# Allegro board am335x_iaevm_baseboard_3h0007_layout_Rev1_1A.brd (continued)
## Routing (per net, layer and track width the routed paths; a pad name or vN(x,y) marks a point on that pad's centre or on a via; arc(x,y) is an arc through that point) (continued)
AM335X_OSC0_OUT: length 11.4
  TOP w0.121: U2.U11 91.43,86.63 92.82,86.63 93.37,87.17 94.36,87.17 95.32,86.21 98.78,86.21 100.06,84.93 100.52,84.93 R8.1
AM335X_OSC1_IN: length 15.2
  TOP w0.102: 77.74,81.97 77.97,81.97 U2.A6
  TOP w0.121: Y1.4 64.93,79.11 65.71,79.9 65.86,79.9 66.71,80.74 C2.2 67.42,80.77 67.45,80.8 68.46,80.8 68.83,80.43 71.12,80.43 71.35,80.66 72.66,80.66 73.32,81.32 75.69,81.32 76.01,81.64 76.42,81.64 76.43,81.63 77.2,81.63 77.22,81.6 77.36,81.6 77.74,81.97
AM335X_OSC1_OUT: length 8.5
  TOP w0.102: U2.A4 77.91,80.89 77.1,80.89
  TOP w0.121: 77.1,80.89 76.32,80.89 75.34,79.91 71.66,79.91 71.27,79.53 70.95,79.53 70.84,79.41 R5.1
AM335X_PORZ: length 21
  TOP w0.102: 78.08,89.83 78.58,89.83 79,89.41 U2.B15
  TOP w0.121: 78.08,89.83 76.52,89.83 76.16,90.19 v1(76.16,90.46) ; v1(70.52,100.81) 69.57,101.76 R9.2
  BOTTOM w0.121: v1(70.52,100.81) 72.76,100.81 74.33,99.23 74.33,92.29 v1(76.16,90.46)
AM335X_RTC_PORZ: length 43
  TOP w0.102: 76.32,81.39 77.49,81.39 77.86,81.76 78.65,81.76 79,81.41 U2.B5
  TOP w0.121: U1.3 60.48,99.86 v1(60.24,100.11) 60.48,100.36 U1.2 ; 76.32,81.39 76.12,81.39 75.79,81.06 73.44,81.06 72.79,80.41 71.45,80.41 71.22,80.17 68.73,80.17 68.55,80.36 v1(68.11,80.36)
  LY3 w0.133: v1(68.11,80.36) 62.21,80.36 61.93,80.64 v1(61.93,80.68)
  BOTTOM w0.121: R4.2 60.74,100.62 v1(60.24,100.11) 59.71,99.59 59.71,97.92 59.22,97.42 59.22,89.66 59.22,89.05 60.36,87.91 60.36,87.52 60.36,87.52 60.36,86.91 61.08,86.18 61.08,83.28 61.71,82.64 61.71,80.9 v1(61.93,80.68)
AM335X_SPI0_CS0: length 77.4
  TOP w0.102: U2.A16 77.1,90.2
  TOP w0.121: 131.23,95.29 129.4,95.29 v1(129.35,95.34) ; v2(76.9,90.25) 76.94,90.2 77.1,90.2
  LY3 w0.133: v1(72.13,100.28) 73.56,101.7 82.75,101.7 83.22,101.23 92.14,101.23 97.11,96.25 116.29,96.25 117.21,95.34 v1(129.35,95.34)
  BOTTOM w0.121: v1(72.13,100.28) 72.73,99.68 72.73,96.78 72.17,96.22 R552.1 72.77,95.58 73.38,95.58 74.08,94.87 74.08,91.91 76.03,89.97 76.62,89.97 v2(76.9,90.25)
AM335X_SPI0_CS1: length 10.4
  TOP w0.102: v2(79.4,89.8) U2.C15
  TOP w0.121: v1(73.01,90.83) 73.02,90.84 73.02,91.16 72.61,91.56 72.61,91.82 72.3,92.13 R380.2 72.29,92.19 71.33,92.19 R78.2
  BOTTOM w0.102: 77.1,89.72 79.32,89.72 v2(79.4,89.8)
  BOTTOM w0.121: 77.1,89.72 73.73,89.72 73.01,90.44 v1(73.01,90.83)
AM335X_SPI0_D0: length 107.8
  TOP w0.102: U2.B17 78.67,91.33 77.33,91.33 77.21,91.45 77.1,91.45
  TOP w0.121: v1(76.11,133.44) 78.83,133.44 R205.1 ; 77.1,91.45 75.89,91.45 v1(75.63,91.71)
  BOTTOM w0.121: v1(76.11,133.44) 76.11,133.45 75.98,133.58 70.52,133.58 70.4,133.45 70.4,133.06 70.52,132.93 75.2,132.93 75.32,132.8 75.32,132.4 75.2,132.27 70.52,132.27 70.4,132.14 70.4,131.79 70.52,131.66 75.4,131.66 75.53,131.53 75.53,131.15 75.4,131.02 70.52,131.02 70.4,130.9 70.4,130.52 70.52,130.39 75.6,130.39 75.73,130.26 75.73,129.91 75.6,129.78 70.85,129.78 70.73,129.65 70.73,129.26 70.85,129.13 73.6,129.13 73.72,129 73.72,120.18 75.98,117.92 75.98,111.75 76.11,111.62 76.34,111.62 76.47,111.49 76.47,105.7 76.34,105.57 75.96,105.57 75.83,105.7 75.83,110.76 75.7,110.88 75.27,110.88 75.14,110.76 75.14,105.07 75.27,104.94 75.99,104.94 76.12,104.81 76.12,104.35 75.99,104.23 75.27,104.23 75.14,104.1 75.14,103.64 75.27,103.52 76.02,103.52 76.14,103.39 76.14,102.96 76.02,102.83 75.27,102.83 75.14,102.7 75.14,102.31 75.98,101.47 75.98,100.14 75.37,99.53 75.37,97.67 75.25,97.54 74.71,97.54 74.58,97.41 74.58,96.73 74.71,96.61 75.61,96.61 75.74,96.48 75.74,95.8 75.61,95.67 74.71,95.67 74.58,95.54 74.58,92.39 75.27,91.71 v1(75.63,91.71)
AM335X_SPI0_D1: length 15
  TOP w0.102: U2.B16 78.67,90.2 78.28,90.59 77.24,90.59 77.1,90.73
  TOP w0.121: R177.1 71.54,93.76 71.99,93.32 72.37,93.32 v1(72.81,92.87) 73.06,92.62 73.74,92.62 75.46,90.9 76.92,90.9 77.1,90.73
  BOTTOM w0.121: v1(72.81,92.87) 72.81,94.4 R553.1
AM335X_SPI0_SCLK: length 8
  TOP w0.102: 77.1,91.13 77.23,91 U2.A17 ; 77.08,91.15 76.87,91.15
  TOP w0.121: 77.1,91.13 77.08,91.15 ; 76.87,91.15 75.56,91.15 72.44,94.27 R201.1
AM335X_UART0_CTSN: length 13.9
  TOP w0.102: U2.E18 81.51,91.91 81.51,92.78
  TOP w0.121: 81.51,92.78 80.93,93.36 80.93,95.53 81.07,95.67 81.07,96.86 81.94,97.74 81.94,98.43 81.27,99.11 81.27,99.89 79.29,101.87 79.29,103.16 R61.2
AM335X_UART0_RTSN: length 10.7
  TOP w0.102: 80.68,92.9 80.68,92.37 81.06,91.99 81.06,91.35 81.4,91.01 U2.E17
  TOP w0.121: 80.68,92.9 80.68,95.72 80.82,95.85 80.82,96.99 81.66,97.83 81.66,97.83 81.69,97.87 81.69,98.33 80.79,99.23 80.17,99.23 R362.2
AM335X_UART0_RXD: length 103.8
  TOP w0.102: v2(81,89.8) U2.E15
  TOP w0.121: v1(78.64,105.09) 78.44,104.9 78.13,104.9 77.35,104.12 77.35,103.52 78.4,102.48 78.4,100.2 78.15,99.95 78.15,99.52 78.57,99.1 79.16,99.1 R363.2 80.17,97.43 80.57,97.03 80.57,96.04 80.22,95.69 v1(80.22,95.46) ; v1(52.62,64.73) 52.62,62.9 R249.2
  LY3 w0.133: v1(51.14,107.12) 51.48,107.46 51.48,107.59 51.74,107.85 51.87,107.85 51.9,107.89 53.17,107.89 54.52,106.54 77.13,106.54 78.56,105.1 78.62,105.1 v1(78.64,105.09)
  BOTTOM w0.102: v2(81,89.8) 81,89.83 80.58,90.24 80.58,90.97 ; 80.35,93.04 80.35,91.2 80.54,91.01
  BOTTOM w0.121: 80.54,91.01 80.58,90.97 ; v1(80.22,95.46) 80.22,95.22 80.35,95.08 80.35,93.04 ; v1(51.14,107.12) 47.43,107.12 44.84,104.53 44.84,103.38 44.81,103.35 44.81,98.78 44.64,98.61 44.64,94.02 45.12,93.53 45.12,80.81 44.35,80.04 43.12,78.8 43.12,72.96 48.45,67.63 50.56,67.63 52.62,65.57 v1(52.62,64.73)
AM335X_UART0_TXD: length 14.6
  TOP w0.102: v2(81,90.6) U2.E16
  TOP w0.121: v1(78.84,96.15) 78.42,96.57 73.31,96.57 R361.2
  BOTTOM w0.102: v2(81,90.6) 81,91.15 80.66,91.49 80.66,92.9
  BOTTOM w0.121: 80.66,92.9 80.66,95.67 80.4,95.92 79.08,95.92 78.85,96.15 v1(78.84,96.15)
AM335X_UART1_CTSN: length 17
  TOP w0.102: 80.41,91.99 U2.D18
  TOP w0.121: 80.41,91.99 80.41,94.64 79.77,95.28 79.77,96 80.13,96.36 v1(80.13,96.36) ; R84.2 75.86,103.54 76.56,103.54 v1(76.56,103.54)
  BOTTOM w0.121: v1(80.13,96.36) 79.99,96.36 79.77,96.58 79.31,96.58 79.08,96.81 79.08,99.07 78.9,99.25 78.9,100.66 79.46,101.22 79.46,102.2 78.62,103.03 77.07,103.03 v1(76.56,103.54)
AM335X_UART1_RTSN: length 15.2
  TOP w0.102: U2.D17 80.59,91 80.24,91.35 80.24,91.85
  TOP w0.121: v1(76.7,101.23) 76.7,100.95 R229.1 76.74,99.99 76.74,98.34 77.57,97.51 79.68,97.51 79.68,97.51 79.75,97.51 80.01,97.25 80.01,96.88 79.53,96.4 79.53,95.18 80.17,94.54 80.17,91.92 80.24,91.85
  BOTTOM w0.121: v1(76.7,101.23) 77.18,101.23 77.76,100.65 77.76,100.62
AM335X_UART1_RXD: length 15.1
  TOP w0.102: v2(80.2,90.6) U2.D16
  TOP w0.121: v1(75.93,98.94) 75.65,99.23 73.16,99.23 72.68,99.71 72.68,99.73
  LY4 w0.102: v2(80.2,90.6) 79.42,91.38 78.02,91.38 77.61,91.78 77.61,92.75 77.46,92.9
  LY4 w0.133: 77.46,92.9 77.46,94.83 76.69,95.59 76.69,98.18 v1(75.93,98.94)
AM335X_UART1_TXD: length 13.8
  TOP w0.102: v2(80.2,89.8) U2.D15
  TOP w0.121: R91.2 74.84,97.9 v1(74.92,97.98)
  LY4 w0.102: v2(80.2,89.8) 80.2,89.83 79.81,90.22 77.7,90.22 77.1,90.82
  LY4 w0.133: v1(74.92,97.98) 74.93,97.97 74.93,91.36 75.35,90.94 76.97,90.94 77.1,90.82
AM335X_USB0_CE: length 13.7
  TOP w0.102: v2(87.4,89.8) U2.M15
  TOP w0.121: TP23.1 93.14,98.59 93.64,99.09 v1(93.64,99.1)
  LY3 w0.133: v2(87.4,89.8) 87.4,89.81 87.8,90.21 87.8,90.46 87.8,90.46 87.8,90.76 87.86,90.82 87.86,93.17 90.44,95.74 90.44,96.68 92.87,99.12 93.61,99.12 v1(93.64,99.1)
AM335X_USB0_DRVVBUS: length 108.1
  TOP w0.102: U2.F16 v2(81.8,90.6)
  TOP w0.121: U22.4 137.87,145.15 v1(138.42,144.6)
  LY3 w0.133: v1(138.42,144.6) 137.36,143.55 121.45,143.55 118.66,140.75 101.51,140.75 95.52,134.76 84.87,134.76 v1(84.01,133.9)
  LY4 w0.133: v2(81.8,90.6) 81.8,90.71 80.12,92.39 80.12,94.7 79.55,95.28 79.55,96.41 80.01,96.88 80.01,97.61 79.74,97.88 79.74,103.74 80.68,104.68 80.68,116.42 83.42,119.15 83.42,133.17 84.01,133.77 v1(84.01,133.9)
  BOTTOM w0.121: R383.1 137.35,144.6 v1(138.42,144.6)
AM335X_USB0_VBUS: length 17.2
  TOP w0.254: D9.1 96.3,96.24 R563.2 ; v2(89,89.8) U2.P15
  TOP w0.508: R563.2 95.99,97.05 v1(94.84,97.05)
  LY3 w0.127: 89.01,91.27 89.41,90.88 89.41,90.21 v2(89,89.8)
  LY3 w0.133: 89.01,91.27 88.6,90.86 88.6,90.2 v2(89,89.8)
  LY3 w0.508: 89.01,91.27 89.01,93.69 91.99,96.66 91.99,97.01 92.47,97.5 94.39,97.5 v1(94.84,97.05)
AM335X_USB1_CE: length 6
  TOP w0.102: U2.P18 88.6,92.9
  TOP w0.121: 88.6,92.9 88.6,93.32 89.79,94.52 90.45,94.52 91.35,95.41 TP36.1
AM335X_USB1_DRVVBUS: length 136.3
  TOP w0.102: U2.F15 v2(81.8,89.8)
  TOP w0.121: U29.4 v1(146.58,144.83)
  LY3 w0.133: v1(81.83,133.87) 82.43,133.26 85.51,133.26 86.6,134.35 95.74,134.35 101.76,140.37 118.91,140.37 121.7,143.17 138.85,143.17 142.53,139.48 142.53,133.77 v1(143.36,132.94)
  LY4 w0.133: v1(81.83,133.87) 81.83,130.15 81.32,129.64 81.32,119.19 80.28,118.15 80.28,104.79 79.03,103.54 79.03,96.76 79.29,96.51 79.29,95.17 79.68,94.78 79.68,92.48 81.4,90.76 81.4,90.2 v2(81.8,89.8)
  BOTTOM w0.121: R387.1 146.21,145.2 v1(146.58,144.83) 146.58,143.09 146.34,142.85 145.33,142.85 145.01,142.53 145.01,137.51 143.42,135.93 143.42,133.01 v1(143.36,132.94)
AM335X_USB1_VBUS: length 12.8
  TOP w0.254: v1(90.37,101.71) 90.37,101.28 D10.1 ; U2.T18 v2(90.2,92.37)
  TOP w0.508: R564.2 90.37,102.73 v1(90.37,101.71)
  LY4 w0.508: v1(90.37,101.71) 90.37,101.22 90.54,101.05 90.54,98.59 89.78,97.83 89.78,94.63 89.37,94.22 89.37,92.94 89.86,92.45 90.12,92.45 v2(90.2,92.37)
AM335X_VDDA_ADC: length 42.7
  TOP w0.381: v2(80.2,83.4) U2.D8
  TOP w0.508: v1(49.31,74.43) v1(59,74.43) ; v1(59.54,81.68) 60.17,81.68 60.28,81.57 64.38,81.57 64.49,81.46 65.8,81.46 66.12,81.79 69.29,81.79 70.21,80.87 70.26,80.87 70.26,80.87 70.79,80.87 71.02,81.1 72.27,81.1 73.32,82.14 76.58,82.14 76.64,82.08 v1(76.82,82.08)
  BOTTOM w0.152: v1(76.82,82.08) 77.19,82.08 77.82,82.71 79.67,82.71 80.2,83.25 v2(80.2,83.4)
  BOTTOM w0.508: v1(59,74.43) 59.54,74.97 59.54,79.68 59.52,79.7 59.52,81.66 v1(59.54,81.68) ; R501.1 v1(49.31,74.43) 49.6,74.71 50.33,74.71
AM335X_VDDS: length 39.8
  TOP w0.305: v2(81,81.8) U2.E6
  TOP w0.381: v2(89,89) U2.P14 ; v2(89,84.2) U2.P9 ; v2(85.8,88.2) U2.K13 ; v2(82.6,84.2) U2.F9 ; U2.E14 v2(81,89) ; v2(88.2,81.8) U2.N6
  TOP w0.635: v1(99.99,111.54) 99.15,111.54 97.08,109.47 88.8,109.47 v1(88.21,108.88)
  LY4 w0.635: v1(87.42,99.11) 87.42,100.27 88.07,100.93 88.07,108.74 v1(88.21,108.88)
  BOTTOM w0.102: 81.42,90.21 82.08,90.21 82.21,90.33 82.21,91.1 C96.1 81.42,91.07 81.42,90.21 ; 81.42,90.21 81.42,89.68 81,89.26 v2(81,89)
  BOTTOM w0.508: C50.1 92.43,89.68 92.71,89.95 92.75,89.95 v1(92.82,90.03) 92.82,90.16 92.45,90.52 C48.1
  BOTTOM w0.635: C249.1 99.99,110.43 v1(99.99,111.54) 99.99,112.18 C89.1 100.75,115.32 R498.1
  vias: v1(93.43,90.33)
AM335X_VDDS_DDR: length 54.2
  TOP w0.381: U2.E5 v2(81.8,81) U2.F5 ; U2.K5 v2(85.8,81) U2.L5 ; U2.H5 v2(84.2,81) U2.J5 ; v2(82.6,81) U2.G5
  TOP w0.635: R508.2 115.7,69.44 116.29,68.85 116.29,65.75 115.6,65.06 110.78,65.06 110.78,65.17 108.24,67.71 C233.1 104.73,68.43 104.44,68.43 103.95,68.92 103.95,70.67 101.75,72.87 98.99,72.87 98.74,73.13 v1(97.62,73.13) v1(97.04,73.13) v1(96.43,73.13)
  LY3 w0.635: v1(96.43,73.13) v1(97.04,73.13) v1(97.62,73.13)
  LY4 w0.635: 92.34,82.38 92.65,82.08 93.54,82.08 94.02,81.6 94.02,80.56 94.53,80.05 94.53,77.76 96.43,75.86 v1(96.43,73.13) v1(97.04,73.13) v1(97.62,73.13)
  BOTTOM w0.381: v2(81.8,81) 81.76,81.04 C77.1 ; C79.1 84.26,80.94 v2(84.2,81) ; C78.1 85.86,80.94 v2(85.8,81) ; C82.1 v1(97.62,73.13) ; v1(96.43,73.13) 96.31,73 95.61,73 C80.1 ; v2(82.6,81) 83.3,81.7 C76.1
  BOTTOM w0.635: v1(96.43,73.13) v1(97.04,73.13) v1(97.62,73.13)
AM335X_VDDSHV1: length 54
  TOP w0.381: U2.P8 v2(89,83.4) U2.P7
  LY3 w0.102: 91.74,82.52 91.43,82.21 89.45,82.21 89,82.65 v2(89,83.4) 89.26,83.4 89.64,83.02 89.65,83.02 89.69,82.98 91.29,82.98
  LY3 w0.508: 91.29,82.98 92.06,82.21 95.67,82.21 98.34,79.54 99.16,79.54 99.8,80.17 v1(99.99,80.17) 100.62,80.81 100.62,81.95 101.38,82.71 v1(102.91,82.71) 103.54,83.35 107.1,83.35 v1(108.37,82.08)
  BOTTOM w0.381: C31.1 88.31,83.4 v2(89,83.4)
  BOTTOM w0.508: v1(99.99,80.17) 100.49,79.67 101.38,79.67 101.65,79.4 C258.1 ; C32.1 103.8,82.71 v1(102.91,82.71) ; v1(108.37,82.08) 115.48,74.97 120.69,74.97 122.11,73.54 R493.1
AM335X_VDDSHV2: length 39.3
  TOP w0.381: U2.P10 88.6,85.46 88.72,85.58 88.72,86.02 88.6,86.14 U2.P11 v2(89,86.6)
  TOP w0.508: C259.1 97.89,86.7 v1(95.85,86.7) 95.85,87.59 C92.1
  LY3 w0.635: v1(115.42,95.03) 110.5,95.03 108.29,92.82 102.4,92.82 101.12,91.54 101.12,89.74 99.11,87.73 96.87,87.73 v1(95.85,86.7) 95.07,86.7 94.73,87.04 93.69,87.04 93,86.35 93,86.35 92.45,85.8 89.68,85.8 89.15,86.33 89.15,86.45 v2(89,86.6)
  BOTTOM w0.381: C90.1 89,85.95 v2(89,86.6)
  BOTTOM w0.635: R545.1 114.43,95.03 v1(115.42,95.03)
AM335X_VDDSHV3: length 96.8
  TOP w0.381: v2(89,88.2) U2.P13 ; U2.P12 v2(89,87.4)
  TOP w0.635: R546.1 v1(135,140.59)
  LY3 w0.635: v1(110.65,135.93) 132.24,135.93 134.4,138.09 134.4,139.99 v1(135,140.59) ; 93.17,87.97 93.24,87.97 93.28,87.92 94.97,87.92 96.42,89.37 v1(96.48,89.37) 96.85,89.37 97.14,89.66 97.14,90.06 97.18,90.1 97.18,90.67 97.14,90.71 97.14,90.99 97.94,91.79 99.54,91.79 100.37,92.62 100.9,92.62 101.87,93.59 v1(102.31,93.59) 102.54,93.81 107.65,93.81 108.77,94.93 v1(108.77,95.13)
  LY4 w0.635: v1(110.65,135.93) 109.89,135.17 109.89,105.57 111.54,103.92 111.54,101.15 110.55,100.16 110.55,96.71 108.97,95.13 v1(108.77,95.13)
  BOTTOM w0.381: v2(89,87.4) v2(89,88.2) 88.28,88.2 C94.1
  BOTTOM w0.508: C273.1 102.85,93.59 v1(102.31,93.59) ; C93.1 97.19,90 96.56,89.37 v1(96.48,89.37)
AM335X_VDDSHV4: length 99.8
  TOP w0.381: U2.J14 v2(84.2,89) U2.H14
  TOP w0.635: v1(122.47,133.7) 130.47,133.7 131.1,133.07 v1(133.58,133.07)
  LY3 w0.635: v1(119.67,116.06) 118.2,114.59 v1(83.13,114.59)
  LY4 w0.635: v2(84.2,89) 84.53,89 84.92,89.39 84.92,91.25 85.56,91.88 85.56,94.3 85.1,94.75 85.08,94.75 84.49,95.34 84.49,95.54 v1(84.44,95.59)
  BOTTOM w0.635: v1(83.13,114.59) 83.13,97.21 83.64,96.7 C274.1 v1(84.44,95.59) 83.6,94.75 C43.1 ; v1(133.58,133.07) 134.69,133.07 R494.1 ; C42.1 84.07,89.13 v2(84.2,89) ; v1(119.67,116.06) 119.73,116.13 119.73,129.64 122.47,132.37 v1(122.47,133.7)
AM335X_VDDSHV5: length 73.1
  TOP w0.381: U2.K14 v2(85.8,89) U2.L14
  TOP w0.635: v1(94.35,131.23) 94.58,131 97.97,131 v1(98.65,131.69)
  LY4 w0.102: v2(85.8,89) 85.8,89.03 85.42,89.41 85.42,90.82 85.74,91.13 86.18,91.13 86.18,89.38 v2(85.8,89) ; v2(85.8,89) 86.71,89 86.98,89.27 86.98,90.76 86.97,90.77 86.97,91.48
  LY4 w0.508: 86.18,91.13 86.52,91.48 86.97,91.48 88.68,93.19 88.68,94.26 88.71,94.29 88.71,94.53 89.06,94.88 v1(89.06,96.4)
  BOTTOM w0.635: v1(94.35,131.23) 93.71,130.59 93.71,122.21 90.27,118.77 90.27,113.23 90.8,112.7 90.8,108.18 91.79,107.19 91.79,104.42 90.42,103.05 C257.1 91.07,102.31 91.07,101.15 91.6,100.62 91.6,98.52 90.15,97.07 89.06,97.07 v1(89.06,96.4) ; v1(98.65,131.69) 98.72,131.75 98.72,140.63 99.35,141.26 R495.1 ; v2(85.8,89) 85.94,89.14 C46.1
AM335X_VDDSHV6: length 16.9
  TOP w0.381: U2.E10 v2(81,85.8) U2.E11 v2(81,86.6) U2.E12 ; U2.P5 v2(89,81) ; U2.P5 v2(88.2,81) U2.N5 ; U2.P5 v2(89,81.8) U2.P6 ; U2.G14 v2(82.6,89) U2.F14 ; U2.E13 v2(81,88.2)
  TOP w0.635: C28.1 50.33,85.05 v1(50.31,85.07)
  BOTTOM w0.381: 70.9,83.48 70.14,83.48 v1(69.76,83.1) ; C47.1 77.76,90.77 77.2,91.32 v2(77.2,91.88)
  BOTTOM w0.635: C27.1 82.47,89.13 v2(82.6,89) ; C25.1 92.24,81.69 92.37,81.57 v2(92.37,81.37) ; v2(92.91,79.51) 93.1,79.51 93.31,79.29 93.69,79.29 C29.1 ; R496.1 50.31,86.85 v1(50.31,85.07) 51.51,85.07 C247.1
AM335X_XDMA_EVENT_INTR0: length 16
  TOP w0.102: U2.A15 77.27,89.4 77.17,89.5
  TOP w0.121: 77.17,89.5 76.5,89.5 74.83,91.17 v1(73.95,91.17) ; 66.71,95.03 66.74,95.03 67.19,95.49 70.93,95.49 71.46,94.96 73.16,94.96 v1(73.57,94.55)
  BOTTOM w0.121: v1(73.95,91.17) 73.57,91.55 v1(73.57,94.55)
AM335X_XDMA_EVENT_INTR1: length 31.6
  TOP w0.102: v2(80.2,89) U2.D14
  TOP w0.121: R77.2 63.73,92.3 v1(63.66,92.3)
  LY3 w0.133: v1(63.54,95.8) 64.55,96.81 74.71,96.81 v1(75.98,98.08)
  BOTTOM w0.102: v2(80.2,89) 80.2,89.16 79.78,89.58 79.78,89.96 79.53,90.21 79.51,90.21 79.51,90.21 78.17,90.21
  BOTTOM w0.121: v1(75.98,98.08) 75.98,95.44 74.84,94.3 74.84,92.82 75.4,92.26 75.7,92.26 77.75,90.21 78.17,90.21 ; v1(63.66,92.3) 63.54,92.43 v1(63.54,95.8)
CAP_VBB_MPU: length 4.2
  TOP w0.102: U2.C10 79.41,85.79 v2(79.41,85.8)
  BOTTOM w0.102: 77.22,85.8 v2(79.41,85.8)
  BOTTOM w0.121: 77.22,85.8 77.09,85.8 76.62,86.27 C72.1
CAP_VDD_SRAM_CORE: length 12.4
  TOP w0.102: v2(80.2,85) U2.D9
  TOP w0.121: C60.1 70.01,86.66 71.58,86.66 71.95,87.02 74.63,87.02 75.13,86.52 75.75,86.52 76.59,85.68 v1(76.59,85.42)
  BOTTOM w0.102: v2(80.2,85) 79.94,85 79.56,85.38 78.74,85.38 78.56,85.2 77.73,85.2
  BOTTOM w0.121: 77.73,85.2 77.52,85.42 v1(76.59,85.42)
CAP_VDD_SRAM_MPU: length 5.7
  TOP w0.102: v2(80.2,86.6) U2.D11
  BOTTOM w0.102: v2(80.2,86.6) 80.01,86.79 78.26,86.79 77.63,87.42
  BOTTOM w0.121: C71.1 75.85,87.42 77.63,87.42
DDR_A0: length 57.5
  TOP w0.076: U31.H8 v1(93.16,57.44) ; v1(70.94,57.44) U8.H8
  TOP w0.121: v1(85,55.22) 85,56.81 85.64,57.44 85.64,61.91 86.84,63.12 86.84,63.95 86.25,64.54 86.25,66.8 86.25,67.11 83.22,70.14 v1(83.22,70.97)
  BOTTOM w0.076: 75.07,56.74 73.76,58.05 71.51,58.05 70.94,57.47 v1(70.94,57.44) ; 93.62,56.97 v1(93.16,57.44)
  BOTTOM w0.121: v1(83.22,70.97) 81.25,70.97 80.49,71.73 R18.2 ; 93.62,56.97 93.62,56.82 93.75,56.69 94.08,56.69 94.21,56.57 94.21,53.5 94.08,53.38 86.59,53.38 86.46,53.5 86.46,54.83 86.33,54.96 85.7,54.96 85.44,55.22 v1(85,55.22) 81.39,55.22 81.26,55.09 81.25,55.09 80.81,54.65 75.27,54.65 75.14,54.77 75.14,56.29 75.07,56.36 75.07,56.74
DDR_A1: length 70.1
  TOP w0.076: v1(93.61,61.25) 93.61,60.82 93.72,60.7 93.72,60.24 93.85,60.11 96.81,60.11 96.94,59.98 96.94,59.73 97.07,59.6 98.21,59.6 98.34,59.73 98.34,60.24 98.21,60.36 94.27,60.36 93.98,60.65 93.98,61.71 93.85,61.84 U31.H3 ; U8.H3 71.34,60.73 71.16,60.55 ; v1(70.94,61.44) 70.56,61.06 68.71,61.06 68.7,61.04 68.47,61.04
  TOP w0.121: 71.16,60.55 68.49,60.55 68.36,60.68 68.36,60.93 68.47,61.04 ; v1(87.86,62.39) 87.86,61.79 86.77,60.7 86.5,60.7 86.38,60.83 86.38,61.61 87.63,62.86 87.63,63.21 87.75,63.33 88.01,63.33 88.13,63.45 88.13,63.69 88.01,63.81 87.75,63.81 87.63,63.93 87.63,64.17 87.75,64.29 88.01,64.29 88.13,64.41 88.13,64.65 88.01,64.77 87.75,64.77 87.63,64.9 87.63,65.92 87.44,66.11 87.44,66.75 84.17,70.01 84.17,71.03 R21.2
  BOTTOM w0.076: v1(70.94,61.44) 71.35,61.85 71.35,63.22 71.41,63.28 77.91,63.28 ; 89.24,60.69 89.63,60.3 91.22,60.3 91.35,60.43 91.35,60.68 91.48,60.81 92.49,60.81 92.62,60.68 92.62,60.43 92.75,60.3 94.3,60.3 94.4,60.39 94.4,60.52 94.3,60.62 93.74,60.62 93.61,60.74 v1(93.61,61.25)
  BOTTOM w0.121: 77.91,63.28 79.43,63.28 79.8,62.91 80.25,62.91 82.65,62.91 82.95,63.21 84.47,63.21 85.16,62.52 86.21,62.52 86.33,62.39 86.33,62.11 86.46,61.98 87.76,61.98 87.86,62.08 v1(87.86,62.39) 87.54,62.71 87.29,62.71 87.16,62.84 87.16,63.09 87.29,63.22 87.73,63.22 88.56,62.39 88.56,61.95 88.43,61.82 88.43,61.63 89.01,61.05 89.04,61.05 89.16,60.92 89.16,60.77 89.24,60.69
DDR_A2: length 57.1
  TOP w0.076: v1(93.16,59.04) U31.H7 ; v1(70.94,59.04) U8.H7
  TOP w0.121: v1(84.05,58.39) 84.05,58.84 83.92,58.97 83.79,58.97 83.67,59.1 83.67,60.17 83.79,60.3 83.86,60.3 83.99,60.43 83.99,61.96 84.36,62.34 84.36,62.7 84.11,62.95 84.11,66.11 82.66,67.57 82.66,68 81.26,69.4 80.8,69.4 80.37,69.84 80.37,70.59 80.37,70.6 v1(80.37,70.6)
  BOTTOM w0.076: v1(93.16,59.04) 93.45,59.04 93.57,58.91 93.57,58.33 93.45,58.2 93.13,58.2 93,58.33 93,58.46 92.87,58.58 92.68,58.58 92.56,58.46 92.56,58.33 92.43,58.2 92.3,58.2 92.18,58.33 92.18,58.46 92.05,58.58 91.86,58.58 91.73,58.46 91.73,58.33 91.6,58.2 90.97,58.2 90.84,58.33 90.84,58.9 90.72,59.03 90.02,59.03 89.89,58.9 89.89,57.25 89.64,57 89.24,57 ; v1(70.94,59.04) 70.65,59.04 70.52,59.16 70.52,60.49 70.65,60.62 73.79,60.62 74.31,60.1 74.31,59.37 74.52,59.16 77.32,59.16 77.54,58.94 77.67,58.8 77.79,58.8 77.81,58.78 77.91,58.78
  BOTTOM w0.121: 77.91,58.78 81.57,58.78 81.7,58.65 81.7,58.33 81.83,58.2 82.02,58.2 82.14,58.33 82.14,58.65 82.27,58.78 82.46,58.78 82.59,58.65 82.59,58.33 82.71,58.2 83.4,58.2 83.6,58.39 v1(84.05,58.39) 85.32,58.39 85.44,58.27 85.82,58.27 85.87,58.22 86.62,58.22 87.23,57.61 87.65,57.61 87.78,57.48 87.78,55.03 87.91,54.9 88.49,54.9 88.62,55.03 88.62,56.88 88.75,57 89.24,57 ; v1(80.37,70.6) 80.1,70.6 79.23,71.46 78.32,71.46 77.91,71.06 77.35,71.06 R31.2
DDR_A3: length 65.5
  TOP w0.076: U8.J2 v1(70.14,62.24) ; U31.J2 v1(92.36,63.04)
  TOP w0.121: v1(79.79,64.81) 79.79,65.38 77.89,67.28 77.89,68.65 77.26,69.27 74.47,69.27 v1(73.09,70.65)
  BOTTOM w0.076: v1(92.36,63.04) 92.36,62.78 92.49,62.65 92.72,62.65 92.85,62.78 92.85,62.94 93.26,63.35 93.26,64.3 93.38,64.43 93.89,64.43 94.01,64.54 ; 70.81,65.16 70.65,65 70.2,65 70.04,65.16 ; v1(70.14,62.24) 70.1,62.27 69.32,62.27 68.93,62.65 67.28,62.65 67.16,62.78 67.16,65.16 ; 89.24,63.11 89.69,62.66 89.69,62.08 90.26,61.51 91.67,61.51 91.99,61.82 91.99,63.24 92.21,63.47 92.75,63.47 92.87,63.59 92.87,64.72
  BOTTOM w0.121: 70.04,65.16 70.01,65.19 70.01,65.28 69.95,65.34 69.95,65.76 69.83,65.89 68.62,65.89 68.49,66.01 68.49,66.66 68.11,67.04 68.11,67.22 67.99,67.35 67.28,67.35 67.16,67.22 67.16,65.16 ; R33.2 72.81,78.08 72.81,74.11 72.32,73.62 72.32,71.26 72.93,70.65 v1(73.09,70.65) ; 94.01,64.54 94.01,64.82 93.89,64.93 93.09,64.93 92.87,64.72 ; 70.81,65.16 70.9,65.25 70.9,65.56 71.03,65.68 78.92,65.68 v1(79.79,64.81) 79.79,64.59 80.08,64.3 80.36,64.3 80.44,64.22 85.49,64.22 85.68,64.41 86.73,64.41 86.92,64.22 87.79,64.22 87.8,64.21 88.14,64.21 89.24,63.11
DDR_A4: length 60.8
  TOP w0.076: v1(70.14,57.44) U8.J8 ; v1(92.36,57.44) U31.J8
  TOP w0.121: v1(82.59,55.66) 82.59,54.96 82.46,54.84 81.32,54.84 81.19,54.96 81.19,55.79 81.32,55.92 81.82,55.92 81.94,56.04 81.94,64.29 82.44,64.78 82.44,65.58 81.17,66.85 81.17,67.14 80.39,67.91 80.04,67.91 77.69,70.26 77.67,70.26 75.96,70.26 75.48,70.75 R34.2
  BOTTOM w0.076: 91.1,56.69 91.41,57 91.93,57 v1(92.36,57.44) ; v1(70.14,57.44) 70.14,58.02 70.32,58.2 74.84,58.2 76.3,56.74 76.3,56.36
  BOTTOM w0.121: 76.3,56.36 76.3,55.79 76.17,55.66 75.6,55.66 75.48,55.54 75.48,55.16 75.6,55.03 80.56,55.03 80.68,55.16 80.68,55.85 80.81,55.98 82.46,55.98 82.59,55.85 v1(82.59,55.66) 85.38,55.66 85.84,55.21 86.44,55.21 86.71,54.93 86.71,53.76 86.84,53.63 92.62,53.63 92.75,53.76 92.75,55.09 92.62,55.22 91.22,55.22 91.1,55.35 91.1,56.69
DDR_A5: length 69.5
  TOP w0.076: v1(70.14,61.44) U8.J3 ; v1(92.36,62.24) 92.36,61.57 92.49,61.44 92.68,61.44 92.81,61.31 92.81,60.68 92.94,60.55 93.19,60.55 93.32,60.43 93.32,59.69 93.45,59.56 96.63,59.56 96.75,59.68 96.75,59.84 96.63,59.96 93.7,59.96 93.57,60.08 93.57,60.62 93.45,60.74 93.19,60.74 93.06,60.87 93.06,61.53 U31.J3
  TOP w0.121: R35.2 72.3,73.06 72.3,71.34 72.55,71.09 73.36,71.09 74.93,69.52 77.37,69.52 78.14,68.74 78.14,67.65 80.19,65.61 80.19,65.18 80.19,65.18 80.19,65.12 80.23,65.07 80.23,64.62 80.17,64.56 v1(80.17,63.86)
  BOTTOM w0.076: 90.34,61.31 91.77,61.31 92.36,61.91 v1(92.36,62.24) ; 71.19,64.96 71.03,64.81 70.22,64.81 70.09,64.68 70.09,64.49 69.82,64.22 69.38,64.22 69.25,64.1 69.25,63.34 69.13,63.21 68.29,63.21 68.16,63.34 68.16,65.15 68.17,65.16 ; 67.54,65.16 67.54,63.22 67.79,62.97 70.4,62.97 70.52,62.84 70.52,61.56 70.4,61.44 70.14,61.44 v1(70.14,61.44)
  BOTTOM w0.121: 90.34,61.31 90.21,61.31 89.52,62 89.52,62.48 88.04,63.96 88.01,63.96 87.69,63.96 87.68,63.97 86.82,63.97 86.63,64.16 85.79,64.16 85.58,63.95 82.64,63.95 82.55,63.86 v1(80.17,63.86) 79.93,64.11 79.73,64.11 78.4,65.44 71.31,65.44 71.19,65.31 71.19,64.96 ; 67.54,65.16 67.54,66.52 67.66,66.65 68.04,66.65 68.17,66.52 68.17,65.16
DDR_A6: length 52.5
  TOP w0.076: U31.J7 v1(92.36,59.04) 92.36,58.33 92.23,58.2 90.59,58.2 ; v1(70.14,59.04) U8.J7 ; 90.46,56.36 90.46,58.08
  TOP w0.121: 90.46,56.36 90.46,55.28 90.33,55.16 87.54,55.16 87.41,55.28 v1(87.41,58.05) ; v1(83.29,58.79) 83.29,60.24 83.73,60.68 83.73,61.39 83.36,61.76 83.36,62.99 83.62,63.24 83.62,65.91 82.16,67.36 82.16,67.55 80.81,68.91 80.6,68.91 80.45,69.05 79.48,70.03 79.48,70.57 79.27,70.78 v1(78.61,70.78) ; 90.46,58.08 90.59,58.2
  BOTTOM w0.076: 73.81,60.81 74.46,60.16 74.46,59.6 74.71,59.35 77.44,59.35 77.76,59.03 77.91,59.03
  BOTTOM w0.121: v1(70.14,59.04) 70.14,60.68 70.26,60.81 73.81,60.81 ; v1(78.61,70.78) 78.61,70.78 78.4,70.56 75.94,70.56 R36.2 ; 77.91,59.03 82.59,59.03 82.82,58.79 v1(83.29,58.79) 83.82,58.79 83.86,58.83 84.41,58.83 84.48,58.9 85.25,58.9 85.38,58.77 85.39,58.77 85.57,58.59 85.85,58.59 85.98,58.46 87.03,58.46 87.41,58.08 v1(87.41,58.05)
DDR_A7: length 77
  TOP w0.076: 90.72,64.93 90.72,64.62 90.84,64.49 91.83,64.49 91.96,64.36 U31.K2 ; U8.K2 69.74,62.97 69.61,63.09 ; v1(91.56,63.04) 91.51,63.09 91.51,64.11 91.38,64.24 90.4,64.24 90.27,64.36 90.27,65.15 90.28,65.16
  TOP w0.121: 69.61,63.09 68.49,63.09 68.36,62.97 68.36,62.71 68.24,62.58 64.81,62.58 64.68,62.71 64.68,63.11 64.81,63.24 65.45,63.24 65.57,63.36 65.57,63.6 65.45,63.72 64.81,63.72 64.68,63.85 64.68,64.08 64.81,64.21 65.45,64.21 65.57,64.33 65.57,64.57 65.45,64.69 64.79,64.69 64.66,64.82 64.66,66.85 65.17,67.35 67.92,67.35 68.05,67.22 68.05,66.56 68.17,66.44 v1(69.02,66.44) ; 90.72,64.93 90.72,65.06 91.1,65.44 91.52,65.44 91.64,65.32 91.64,64.86 91.76,64.74 92,64.74 92.12,64.86 92.12,65.32 92.24,65.44 92.68,65.44 92.81,65.32 92.81,63.92 92.94,63.79 93.13,63.79 93.26,63.92 93.26,65.32 93.38,65.44 94.72,65.44 94.84,65.57 94.84,65.96 94.72,66.08 94.21,66.08 94.08,66.21 94.08,66.57 93.95,66.69 93.76,66.69 93.64,66.57 93.64,66.21 93.51,66.08 93.32,66.08 93.19,66.21 93.19,66.59 93.06,66.71 92.81,66.71 92.68,66.59 92.68,66.21 92.56,66.08 91.2,66.08 90.28,65.16 ; R37.2 79.29,71.6 79.85,71.04 80.67,71.04 84.56,67.15 v1(84.56,65.89)
  BOTTOM w0.076: 90,64.86 90,64.23 90.01,64.23 90.01,62.19 90.33,61.87 90.91,61.87 91.16,62.11 91.16,62.63 v1(91.56,63.04)
  BOTTOM w0.121: v1(69.02,66.44) 69.02,66.32 69.14,66.19 69.83,66.19 69.83,66.18 70.2,66.18 70.2,66.19 72.75,66.19 72.76,66.18 79.12,66.18 79.81,65.5 80.34,65.5 80.79,65.95 83.73,65.95 83.79,65.89 v1(84.56,65.89) 85.7,65.89 86.39,65.19 87,65.19 87.23,64.96 88.09,64.96 88.1,64.95 88.88,64.95 88.94,65.01 89.85,65.01 90,64.86
DDR_A8: length 60
  TOP w0.076: U8.K8 v1(69.34,57.44) ; U31.K8 v1(91.56,57.44)
  TOP w0.121: v1(83.86,56.3) 83.22,56.93 83.22,58.23 82.84,58.61 82.84,60.24 83.12,60.51 83.12,63.09 83.37,63.35 83.37,65.81 81.92,67.26 81.92,67.45 80.71,68.66 80.5,68.66 80.21,68.95 79.23,69.93 79.23,70.2 79.17,70.26 v1(79.03,70.26)
  BOTTOM w0.076: 77.91,56.72 77.57,57.06 76.3,57.06 74.97,58.39 70.29,58.39 v1(69.34,57.44) ; 90.91,57.06 91.15,57.31 91.15,57.31 91.28,57.44 v1(91.56,57.44)
  BOTTOM w0.121: 77.91,56.72 78.33,56.3 v1(83.86,56.3) 84.24,55.92 85.35,55.92 85.36,55.91 85.48,55.91 85.94,55.45 86.54,55.45 86.96,55.04 86.96,54.01 87.08,53.89 92.37,53.89 92.49,54.01 92.49,54.84 92.37,54.96 90.97,54.96 90.84,55.09 90.84,57 90.91,57.06 ; R38.2 74.08,75.67 74.08,73.82 74.21,73.7 74.21,71.28 75.18,70.31 78.98,70.31 v1(79.03,70.26)
DDR_A9: length 67
  TOP w0.076: v1(91.56,62.24) 91.54,62.22 91.54,61.63 91.41,61.51 90.02,61.51 89.89,61.38 89.89,60.68 90.02,60.55 90.28,60.55 90.35,60.63 90.35,61.11 90.43,61.19 90.58,61.19 90.66,61.11 90.66,60.63 90.74,60.55 90.89,60.55 90.96,60.63 90.96,61.11 91.04,61.19 91.19,61.19 91.27,61.11 91.27,60.63 91.34,60.55 91.5,60.55 91.57,60.63 91.57,61.11 91.65,61.19 91.8,61.19 91.88,61.11 91.88,60.63 91.95,60.55 92.49,60.55 92.62,60.68 92.62,61.19 92.52,61.29 92.09,61.29 91.96,61.42 U31.K3 ; v1(69.34,61.44) U8.K3
  TOP w0.121: v1(81.99,65.15) 81.99,65.68 80.92,66.75 80.92,67.04 80.29,67.66 79.92,67.66 77.57,70.01 77.37,70.01 75.47,70.01 74.52,70.96 R39.2 ; v1(66.27,63.09) 66.01,63.09 65.89,63.22 65.89,64.87 65.76,65 65.06,65 64.93,65.12 64.93,66.65 65.32,67.03 67.54,67.03 67.66,66.9 67.66,66.08 67.79,65.95 69.95,65.95 v1(70.4,65.51)
  BOTTOM w0.076: 89.33,63.97 89.74,63.97 89.85,63.85 89.85,63.57 89.73,63.44 89.57,63.44 89.45,63.32 89.45,63.12 89.85,62.72 89.85,62.14 90.33,61.66 91.54,61.66 91.67,61.78 91.67,62.13 v1(91.56,62.24) ; 67.01,62.35 67.54,61.82 68.93,61.82 69.32,61.44 v1(69.34,61.44)
  BOTTOM w0.121: v1(66.27,63.09) 67.01,62.35 ; v1(70.4,65.51) 70.82,65.93 72.07,65.93 72.08,65.94 72.65,65.94 72.66,65.93 79.02,65.93 79.7,65.25 80.2,65.25 80.45,65 81.85,65 v1(81.99,65.15) 82.04,65.19 82.47,65.19 82.59,65.07 82.59,64.58 82.71,64.46 82.95,64.46 83.07,64.58 83.07,65.07 83.19,65.19 83.43,65.19 83.55,65.07 83.55,64.58 83.67,64.46 83.91,64.46 84.03,64.58 84.03,65.07 84.15,65.19 84.4,65.19 84.52,65.07 84.52,64.58 84.64,64.46 84.88,64.46 85,64.58 85,65.06 85.13,65.19 85.64,65.19 85.76,65.06 85.76,64.87 85.95,64.68 86.81,64.68 87.03,64.46 87.89,64.46 87.9,64.45 88.21,64.45 89.13,64.45 89.24,64.34 89.24,64.2 89.25,64.19 89.25,64.05 89.33,63.97
DDR_A10: length 68.2
  TOP w0.076: U8.H2 71.34,64.62 71.02,64.93 68.43,64.93 68.3,64.81 68.3,64.36 68.43,64.24 70.52,64.24 70.85,63.91 70.85,62.32 v1(70.94,62.24) ; U31.H2 93.56,62.27 93.43,62.14 93.26,62.14 93.13,62.27 93.13,63.47 93.26,63.6 93.43,63.6 93.56,63.73 93.56,64.25 93.69,64.38 93.89,64.38 94.02,64.5 94.02,64.68 93.89,64.81 93.6,64.81 93.51,64.9 93.51,65.03 93.6,65.12 94.84,65.12 94.97,65 94.97,64.43 94.84,64.3 94.46,64.3 94.33,64.17 94.33,63.98 94.46,63.85 94.84,63.85 94.97,63.73 94.97,63.36 94.64,63.03 94.08,63.03 93.95,62.9 93.95,62.24 v1(93.96,62.24)
  LY3 w0.133: v1(80.62,73.82) 81.19,73.25 81.19,71.47 85.95,66.71 85.95,64.14 86.16,63.93 v1(86.16,63.41)
  BOTTOM w0.076: v1(70.94,62.24) 70.94,63.34 71.06,63.47 77.49,63.47 77.91,63.89 ; v1(93.96,62.24) 93.96,63.09 93.83,63.22 93.57,63.22 93.45,63.09 93.45,61.61 93.24,61.4 93.24,61.1 93.45,60.9 93.45,60.55 93.34,60.45 93,60.45 92.87,60.58 92.87,60.84 92.75,60.97 91.22,60.97 91.1,60.84 91.1,60.58 90.97,60.45 90.72,60.45 90.59,60.58 90.59,60.84 90.46,60.97 90.27,60.97 90.14,60.84 90.14,60.58 90.02,60.45 89.83,60.45 89.68,60.6 89.68,61.25 89.55,61.38 89.32,61.38 89.24,61.3
  BOTTOM w0.121: 77.91,63.89 77.94,63.92 78.94,63.92 79.25,63.61 79.34,63.61 79.35,63.6 79.46,63.6 79.89,63.17 79.9,63.17 79.91,63.16 82.55,63.16 82.84,63.46 85.83,63.46 85.88,63.41 v1(86.16,63.41) 86.16,62.9 86.28,62.78 86.78,62.78 86.91,62.9 86.91,63.34 87.03,63.46 87.83,63.46 88.81,62.49 88.81,61.59 89.11,61.3 89.24,61.3 ; v1(80.62,73.82) 79.79,73 R40.2
DDR_A11: length 69.1
  TOP w0.076: v1(69.34,59.04) U8.K7 ; 90.72,58.46 90.84,58.58 90.84,58.77 91.1,59.02 91.1,59.22 90.97,59.35 89.57,59.35 89.47,59.45 89.47,59.69 89.57,59.79 91.99,59.79 92.11,59.66 92.11,59.35 91.99,59.22 91.69,59.22 91.56,59.09 v1(91.56,59.04) U31.K7
  TOP w0.121: R41.2 81.19,71.79 86,66.98 86,64.44 86.6,63.84 86.6,63.23 85.39,62.02 85.39,59.8 v1(84.94,59.35) ; 90.72,58.46 90.27,58.46 90.14,58.33 90.14,57.98 90.02,57.86 89.11,57.86 88.99,57.74 88.99,57.5 89.11,57.38 90.02,57.38 90.14,57.26 90.14,57.02 90.02,56.9 89.11,56.9 88.99,56.78 88.99,56.54 89.11,56.41 90.02,56.41 90.14,56.29 90.14,55.6 90.02,55.47 89.59,55.47 89.47,55.59 89.47,55.92 89.34,56.04 89.1,56.04 88.98,55.92 88.98,55.59 88.86,55.47 87.98,55.47 87.86,55.6 87.86,56.08 87.98,56.2 88.44,56.2 88.56,56.32 88.56,56.56 88.44,56.68 87.98,56.68 87.86,56.8 87.86,57.92 87.98,58.05 v1(88.56,58.05)
  BOTTOM w0.076: 77.91,59.32 77.7,59.54 74.9,59.54 74.65,59.79 74.65,60.18 73.99,60.85 73.99,60.88 73.88,60.98 73.85,60.98 73.84,61 69.89,61 69.76,60.87 69.76,60.62 69.63,60.49 69.38,60.49 69.25,60.62 69.25,60.87 69.13,61 68.87,61 68.74,60.87 68.74,60.62 68.62,60.49 68.43,60.49 68.3,60.62 68.3,60.87 68.17,61 67.98,61 67.86,60.87 67.86,60.22 67.98,60.09 69.82,60.09 69.95,59.96 69.95,59.66 69.82,59.54 68.17,59.54 68.05,59.41 68.05,59.16 68.17,59.03 69.33,59.03 v1(69.34,59.04)
  BOTTOM w0.121: v1(88.56,58.05) 88.56,58.52 88.37,58.71 86.08,58.71 85.51,59.28 85,59.28 v1(84.94,59.35) 84.87,59.28 77.95,59.28 77.91,59.32
DDR_A12: length 69.1
  TOP w0.076: U8.L2 v1(68.54,62.24) 67.01,62.24 ; v1(90.76,63.03) 90.33,63.46 90.33,63.79 90.21,63.92 89.45,63.92 89.32,63.79 89.32,63.47 89.45,63.35 90.08,63.35 90.21,63.22 90.21,63.03 90.08,62.9 89.45,62.9 89.32,62.78 89.32,62.52 89.45,62.39 90.4,62.39 90.61,62.6 91.13,62.6 U31.L2
  TOP w0.121: 67.01,62.24 64.71,62.24 64.42,62.53 64.42,66.96 65.12,67.66 68.43,67.66 68.55,67.54 v1(68.55,67.22) ; v1(81,70.01) 83.38,67.63 83.38,67.51 v1(83.86,67.03)
  BOTTOM w0.076: 95.73,65.14 90.51,65.14 90.38,65.01 90.38,64.49 90.46,64.42 90.46,64.05 90.39,63.99 90.39,63.68 90.46,63.62 90.46,63.6 90.76,63.3 v1(90.76,63.03)
  BOTTOM w0.121: v1(68.55,67.22) 71.03,67.22 71.16,67.09 71.16,66.81 71.28,66.68 72.96,66.68 72.97,66.67 79.33,66.67 79.8,66.21 80.3,66.21 81.12,67.03 v1(83.86,67.03) 86.08,67.03 86.33,66.78 87.73,66.78 87.86,66.65 87.86,65.58 87.98,65.45 88.3,65.45 88.31,65.45 88.68,65.45 88.87,65.64 89.25,65.64 89.37,65.76 90.3,65.76 90.42,65.64 92.37,65.64 92.37,65.63 95.73,65.63 95.86,65.51 95.86,65.26 95.73,65.14 ; R42.2 76.65,70.81 78.02,70.81 78.43,71.22 79.13,71.22 80.33,70.01 v1(81,70.01)
DDR_A13: length 68.3
  TOP w0.076: U31.L8 90.89,57.84 90.76,57.71 90.76,56.36 ; v1(68.54,57.44) U8.L8
  TOP w0.121: v1(86.84,56.32) 86.59,56.32 86.46,56.2 86.46,53.82 86.59,53.69 87.25,53.69 87.38,53.82 87.38,54.72 87.5,54.84 87.74,54.84 87.86,54.72 87.86,53.82 87.98,53.69 88.22,53.69 88.34,53.82 88.34,54.72 88.46,54.84 88.7,54.84 88.82,54.72 88.82,53.82 88.94,53.69 89.19,53.69 89.31,53.82 89.31,54.72 89.43,54.84 89.67,54.84 89.79,54.72 89.79,53.82 89.91,53.69 91.16,53.69 91.29,53.82 91.29,54.58 91.41,54.7 93.45,54.7 93.57,54.83 93.57,55.98 93.45,56.11 90.89,56.11 90.76,56.23 90.76,56.36
  LY3 w0.133: v1(85.44,56.55) 85.88,56.99 85.88,61.81 87.09,63.02 87.09,64.05 86.95,64.19 86.33,64.81 86.33,66.84 81.7,71.47 81.7,71.87 81.88,72.05 81.88,73.28 81.51,73.65 v1(81.51,73.89)
  BOTTOM w0.076: 77.91,57.12 77.72,57.31 77.26,57.31 76,58.57 67.31,58.57 67.16,58.42 67.16,57.56 67.28,57.44 v1(68.54,57.44)
  BOTTOM w0.121: v1(86.84,56.32) 86.61,56.55 v1(85.44,56.55) 85.06,56.16 84.61,56.16 84.04,56.74 83.91,56.74 83.91,56.74 83.48,56.74 83.29,56.55 78.48,56.55 77.91,57.12 ; v1(81.51,73.89) 81.51,73.89 81.19,74.21 R43.2
DDR_A14: length 77.6
  TOP w0.076: U8.L3 v1(68.54,61.44) 67.01,61.44 ; v1(90.76,62.24) 89.51,62.24 89.45,62.17 89.45,60.68 89.32,60.55 89.24,60.55 ; U31.L3 89.83,61.84 89.7,61.71 89.7,60.49 89.83,60.36 92.95,60.36 93.06,60.25 93.06,60.11 92.94,59.98 92.94,59.79 93.13,59.6 93.13,59.54 93,59.41 92.49,59.41 92.37,59.54 92.37,59.85 92.24,59.98 89.45,59.98 89.32,59.85 89.32,59.22 89.45,59.09 90.54,59.09 90.65,58.98 90.65,58.82 90.54,58.71 89.95,58.71 89.83,58.58 89.83,58.2 89.73,58.11
  TOP w0.121: 89.24,60.55 89.13,60.55 89,60.43 89,60.24 88.87,60.11 88.62,60.11 88.49,59.98 88.49,59.66 88.62,59.54 88.87,59.54 89,59.41 89,59.16 88.87,59.03 88.55,59.03 88.37,58.85 88.37,58.71 88.49,58.58 88.87,58.58 89,58.46 89,58.2 89.09,58.11 89.73,58.11 ; v1(70.01,66.63) 68.66,67.98 65.12,67.98 65.05,67.91 65.02,67.91 64.17,67.06 64.17,62.4 65.13,61.44 67.01,61.44
  LY3 w0.133: v1(82.4,73.82) 82.4,73.32 82.97,72.74 83.01,72.74 83.79,71.96 83.79,70.78 86.94,67.64 v1(86.94,65.63)
  BOTTOM w0.076: 90.18,65.16 90.18,62.36 90.31,62.24 v1(90.76,62.24)
  BOTTOM w0.121: R44.2 82.4,74.4 v1(82.4,73.82) ; 90.18,65.16 90.18,65.41 90.08,65.51 89.47,65.51 89.35,65.39 88.97,65.39 88.78,65.2 88.21,65.2 88.2,65.21 87.71,65.21 87.54,65.38 87.54,66.39 87.41,66.52 87.07,66.52 86.94,66.39 v1(86.94,65.63) 86.3,65.63 85.8,66.13 85.25,66.13 85.06,66.33 80.79,66.33 80.43,65.96 79.69,65.96 79.23,66.43 72.86,66.43 72.85,66.44 70.7,66.44 70.51,66.63 v1(70.01,66.63)
DDR_BA0: length 61.6
  TOP w0.076: U8.G2 72.49,62.64 72.68,62.83 72.68,63.09 72.65,63.12 71.86,63.12 71.74,62.99 v1(71.74,62.24) ; v1(94.76,62.24) U31.G2
  TOP w0.121: v1(72.39,70.57) 71.92,70.1 71.92,68.43 72.05,68.3 73.32,68.3 73.44,68.43 73.44,68.87 73.57,68.99 77.19,68.99 77.57,68.61 77.57,67.16 79.29,65.44 79.29,64.05 80.05,63.28 v1(80.05,62.46)
  BOTTOM w0.076: v1(94.76,62.24) 93.98,61.45 93.98,60.93 94.11,60.81 94.46,60.81 94.59,60.68 94.59,60.24 94.46,60.11 89.47,60.11 89.24,60.34 ; 77.91,62.37 77.34,62.37 77.25,62.46 77.25,62.59 77.34,62.68 77.91,62.68 ; 77.91,63.04 77.85,63.09 71.6,63.09 71.5,62.99 71.5,62.34 71.6,62.24 v1(71.74,62.24)
  BOTTOM w0.121: 77.91,62.68 79.31,62.68 79.41,62.78 79.41,62.93 79.31,63.04 77.91,63.04 ; 89.24,60.34 88.91,60.66 88.91,60.79 87.97,61.73 86.36,61.73 85.83,62.27 85.06,62.27 84.37,62.96 83.29,62.96 82.89,62.57 80.15,62.57 v1(80.05,62.46) 79.96,62.37 77.91,62.37 ; v1(72.39,70.57) 72.37,70.59 72.36,70.59 72.07,70.87 72.07,73.73 72.56,74.21 72.56,78.09 72.49,78.16 72.49,78.71 R47.2
DDR_BA1: length 74.8
  TOP w0.076: v1(94.35,61.25) 94.35,60.68 94.47,60.55 98.4,60.55 98.53,60.43 98.53,59.71 98.64,59.6 98.79,59.6 98.91,59.71 98.91,60.62 99.03,60.74 99.21,60.74 99.34,60.62 99.34,59.73 99.46,59.6 99.86,59.6 99.99,59.73 99.99,59.92 99.8,60.11 99.8,60.68 99.29,61.19 99.03,61.19 98.91,61.07 98.61,61.07 98.49,61.19 98.23,61.19 98.11,61.07 97.81,61.07 97.69,61.19 97.43,61.19 97.31,61.07 97.01,61.07 96.89,61.19 96.63,61.19 96.51,61.07 96.21,61.07 96.09,61.19 95.83,61.19 95.71,61.07 94.97,61.07 94.84,61.19 94.84,61.71 94.72,61.84 U31.G3 ; 67.01,59.66 71.92,59.66 72.14,59.88 U8.G3 ; 67.01,60.3 71.6,60.3 71.73,60.43 71.73,61.43 v1(71.74,61.44)
  TOP w0.121: 67.01,59.66 64.74,59.66 64.62,59.79 64.62,60.17 64.74,60.3 67.01,60.3 ; v1(83.92,62.52) 83.87,62.57 83.87,66.01 82.41,67.47 82.41,67.65 82.12,67.94 80.91,69.16 80.7,69.16 79.79,70.06 79.79,70.65 R49.2
  BOTTOM w0.076: 89.24,59.94 94.52,59.94 94.78,60.2 94.78,61.12 94.65,61.25 v1(94.35,61.25) ; 77.91,62.08 77.86,62.13 77.2,62.13 77.06,62.27 77.06,62.65 76.81,62.9 72.55,62.9 72.11,62.46 72.11,61.84 72.12,61.83 72.12,61.82 v1(71.74,61.44)
  BOTTOM w0.121: 89.24,59.94 88.67,60.5 88.67,60.69 87.87,61.49 86.23,61.49 85.7,62.01 84.43,62.01 v1(83.92,62.52) 83.29,62.52 83.08,62.32 80.54,62.32 80.3,62.08 80.29,62.08 80.23,62.02 79.48,62.02 79.37,62.12 78.52,62.12 78.39,62 77.99,62 77.91,62.08
DDR_BA2: length 60.4
  TOP w0.076: 72.14,64.65 U8.G1 ; 71.63,65.16 71.67,65.12 ; v1(93.96,63.84) U31.G1 ; v1(71.74,63.84) 71.74,64.55
  TOP w0.121: 71.63,65.16 71.54,65.25 71.54,66.14 71.41,66.27 71.16,66.27 71.03,66.39 71.03,67.35 70.9,67.47 70.59,67.47 70.46,67.35 70.46,66.07 70.64,65.89 70.78,65.89 70.9,65.76 70.9,65.23 71.02,65.11 71.09,65.11 71.1,65.1 71.18,65.1 71.74,64.55 ; 71.67,65.12 72.14,64.65 ; R549.2 72.43,75.35 72.43,73.85 72.02,73.44 72.02,71.31 71.62,70.9 71.62,68.81 71.49,68.68 70.52,68.68 70.4,68.55 70.4,67.86 70.52,67.73 73.63,67.73 73.76,67.86 73.76,68.62 73.89,68.74 76.36,68.74 76.49,68.62 76.49,67.73 76.62,67.6 76.62,67.6 76.75,67.47 76.75,66.77 78.52,65 v1(78.52,64.68)
  BOTTOM w0.076: v1(93.96,63.84) 93.53,63.84 93.41,63.71 93.41,63.28 93,62.88 93,61.25 92.87,61.12 90.08,61.12 89.27,61.93
  BOTTOM w0.121: 89.27,61.93 89.27,62.36 89.13,62.5 89.13,62.52 87.94,63.71 87.91,63.71 87.59,63.71 87.58,63.72 86.72,63.72 86.53,63.91 85.89,63.91 85.68,63.71 82.74,63.71 82.45,63.41 80.05,63.41 80.04,63.42 79.99,63.42 79.55,63.86 79.35,63.86 78.91,64.3 78.9,64.3 v1(78.52,64.68) 78.04,65.16 71.6,65.16 71.47,65.03 71.47,63.96 71.6,63.84 v1(71.74,63.84)
DDR_CASN: length 67
  TOP w0.076: U8.G7 v1(71.74,59.04) ; U31.G7 v1(93.96,59.04)
  TOP w0.121: v1(84.44,57.76) 84.94,57.76 85.06,57.89 85.06,58.53 84.94,58.66 84.65,58.66 84.25,59.06 84.25,59.27 84.25,59.79 84.5,60.04 84.75,60.04 84.87,60.16 84.87,62.33 85.26,62.72 85.26,67.21 81.06,71.41 80.49,71.41 80.24,71.67 R13.2
  BOTTOM w0.076: 77.91,57.95 77.85,57.95 77.73,58.08 77.73,58.4 ; 90.33,56.81 90.08,57.06 90.08,58.71 90.21,58.84 90.46,58.84 90.69,58.61 90.69,58.23 90.91,58.01 93.83,58.01 93.96,58.14 v1(93.96,59.04) ; v1(71.74,59.04) 71.47,59.04 71.35,59.16 71.35,59.35 71.22,59.47 70.9,59.47 70.78,59.6 70.78,60.36 70.88,60.46 71.12,60.46 71.22,60.36 71.22,59.85 71.35,59.73 71.86,59.73 71.96,59.83 71.96,60.34 72.08,60.46 73.72,60.46 74.14,60.05 74.14,59.16 74.33,58.97 76.62,58.97 76.75,58.84 76.75,58.75 76.87,58.63
  BOTTOM w0.121: 90.33,56.81 90.33,54.58 90.21,54.46 89.57,54.46 89.45,54.58 89.45,56.49 89.32,56.62 89,56.62 88.87,56.49 88.87,54.58 88.75,54.46 87.66,54.46 87.53,54.58 87.53,57.23 87.41,57.36 86.57,57.36 86.44,57.49 86.44,57.82 86.32,57.95 86.14,57.95 86.02,57.82 86.02,57.38 85.89,57.25 85.38,57.25 85.25,57.38 85.25,57.63 85.13,57.76 84.43,57.76 84.43,57.76 ; 76.87,58.63 77.5,58.63 77.73,58.4 ; 84.43,57.76 84.23,57.95 83.87,57.95 83.75,57.83 83.75,57.69 83.63,57.57 83.39,57.57 83.27,57.69 83.27,57.83 83.15,57.95 82.91,57.95 82.79,57.83 82.79,57.69 82.67,57.57 82.42,57.57 82.3,57.69 82.3,57.83 82.18,57.95 81.94,57.95 81.82,57.83 81.82,57.69 81.7,57.57 80.91,57.57 80.78,57.69 80.78,58.41 80.66,58.53 80.42,58.53 80.3,58.41 80.3,57.82 80.17,57.7 79.94,57.7 79.82,57.82 79.82,58.41 79.69,58.53 79.45,58.53 79.33,58.41 79.33,58.01 79.21,57.89 78.98,57.89 78.85,58.01 78.85,58.41 78.73,58.53 78.49,58.53 78.37,58.41 78.37,58.07 78.25,57.95 77.91,57.95 ; 84.43,57.76 v1(84.44,57.76)
DDR_CKE: length 72.4
  TOP w0.076: v1(72.54,62.24) 73.28,62.24 73.38,62.33 73.38,62.84 73.63,63.09 73.93,63.09 74.05,63.22 74.05,64.45 73.89,64.62 72.87,64.62 72.64,64.85 72.64,65.16 ; U31.F2 94.97,62.64 94.84,62.76 94.84,63.02 95.16,63.33 95.34,63.33 95.6,63.07 95.6,62.28 v1(95.56,62.24) ; U8.F2 72.94,64.24 72.81,64.36 72.74,64.36 71.95,65.16
  TOP w0.121: 72.64,65.16 72.64,67.35 72.51,67.47 71.54,67.47 71.35,67.28 71.35,66.71 71.79,66.27 71.79,65.47 71.95,65.32 71.95,65.16
  LY3 w0.133: v1(84.43,61.44) 84.43,62.05 84.61,62.24 84.61,65.18 85.01,65.58 85.01,66.45 84.8,66.65 84.8,66.91 80.43,71.28 80.17,71.28 79.73,71.73 79.73,73 v1(78.84,73.89)
  BOTTOM w0.076: 89.51,59.66 89.58,59.73 94.53,59.73 94.97,60.17 94.97,61.92 95.13,62.08 95.13,62.39 94.97,62.55 94.97,63.34 95.1,63.47 98.11,63.47 98.33,63.68 98.33,63.92 98.46,64.05 99.06,64.05 99.17,63.94 99.17,63.52 99.22,63.47 99.48,63.47 99.61,63.34 99.61,63.12 99.48,62.99 98.59,62.99 98.37,62.78 95.69,62.78 95.56,62.65 v1(95.56,62.24) ; 77.91,61.75 77.86,61.75 77.63,61.97 77.01,61.97 76.9,62.08 76.9,62.59 76.75,62.75 72.64,62.75 72.54,62.65 v1(72.54,62.24)
  BOTTOM w0.121: 77.91,61.75 78.49,61.75 78.62,61.88 79.19,61.88 79.32,61.75 80.38,61.75 80.7,62.07 82.4,62.07 82.52,61.94 82.52,61.57 82.65,61.44 v1(84.43,61.44) 84.63,61.24 85.32,61.24 85.52,61.44 85.89,61.44 86.09,61.24 87.77,61.24 88.42,60.58 88.42,60.4 89.16,59.66 89.51,59.66 ; R537.2 79.29,74.33 v1(78.84,73.89)
DDR_CLK: length 62.8
  TOP w0.095: v1(73.34,57.44) U8.E8 ; v1(84.53,54.36) 84.53,54.81 84.39,54.96 84.39,55.48 84.1,55.77 83.5,55.77 82.8,56.46 82.8,56.86 82.61,57.05 82.61,60.34 82.61,63.21 82.85,63.45 82.95,63.55 82.95,65.9 82.51,66.33 82.41,66.33 81.68,67.07 81.68,67.35 80.61,68.43 80.26,68.43 77.38,71.3 R11.2 ; v1(94.77,58.2) 95.59,58.2 U31.E8
  BOTTOM w0.095: v1(73.34,57.44) 73.46,57.31 73.71,57.31 74.52,56.5 74.52,54.21 74.23,53.92 72.61,53.92 72.3,53.62 72.3,52.88 72.5,52.68 80.94,52.68 82.8,54.55 83.3,54.55 83.4,54.57 83.73,54.57 v1(84.53,54.36) 84.54,54.36 84.82,54.36 84.98,54.21 85.15,54.21 85.44,53.92 85.44,51.5 85.57,51.37 94.07,51.37 94.45,51.75 94.45,56.02 94.48,56.05 94.48,57.18 94.38,57.28 94.38,57.81 94.77,58.19 v1(94.77,58.2)
DDR_CLKN: length 63.6
  TOP w0.095: v1(72.54,57.44) U8.F8 ; v1(94.76,57.44) U31.F8 ; v1(83.58,54.14) 84.01,54.14 84.11,54.24 84.11,55.36 84.07,55.4 84.07,55.41 83.98,55.49 83.38,55.49 82.52,56.35 82.52,56.74 82.33,56.94 82.33,60.22 82.33,63.33 82.67,63.67 82.67,65.78 82.4,66.05 82.3,66.05 81.4,66.95 81.4,67.24 80.49,68.15 80.14,68.15 77.1,71.19 76.55,71.19 76.43,71.32 R12.2
  BOTTOM w0.095: v1(94.76,57.44) 94.76,55.93 94.73,55.9 94.73,51.64 94.18,51.09 85.46,51.09 85.17,51.38 85.17,53.81 85.04,53.93 84.25,53.93 84.05,54.14 v1(83.58,54.14) 83.15,54.14 83.1,54.19 82.84,54.19 81.05,52.4 72.39,52.4 72.02,52.77 72.02,53.73 72.49,54.2 74.12,54.2 74.24,54.33 74.24,56.39 73.76,56.87 73.63,56.87 73.49,57.01 73.19,57.01 v1(72.54,57.44)
DDR_CSN: length 66.6
  TOP w0.076: 93.96,56.36 v1(93.96,57.44) U31.G8 ; v1(71.74,57.44) U8.G8
  TOP w0.121: R538.2 84.05,71.73 84.62,71.16 84.62,70.03 87.68,66.97 87.68,66.21 87.88,66.02 87.88,65.8 88.38,65.3 88.38,61.96 86.72,60.31 86.72,57.07 86.15,56.5 86.15,55.01 86.02,54.87 v1(86.02,54.46) 85.76,54.46 85.64,54.33 85.64,53.5 85.76,53.38 91.48,53.38 91.6,53.5 91.6,54.33 91.73,54.46 91.99,54.46 92.11,54.33 92.11,53.5 92.24,53.38 92.56,53.38 92.68,53.5 92.68,54.33 92.81,54.46 93.06,54.46 93.19,54.33 93.19,53.5 93.32,53.38 93.51,53.38 93.64,53.5 93.64,54.33 93.77,54.46 96.94,54.46 97.07,54.59 97.07,55.28 96.94,55.41 95.47,55.41 95.34,55.29 94.09,55.29 93.96,55.41 93.96,56.36
  BOTTOM w0.076: v1(71.74,57.44) 71.74,57.76 71.86,57.88 73.52,57.88 74.82,56.57 74.82,56.36
  BOTTOM w0.121: 74.82,56.36 74.82,56.26 74.89,56.19 74.89,53.69 74.76,53.57 74.33,53.57 74.21,53.44 74.21,53.06 74.33,52.93 80.86,52.93 81.51,53.58 81.51,54.77 81.63,54.9 84.62,54.9 85.06,54.46 v1(86.02,54.46)
DDR_D0: length 41.6
  TOP w0.076: U8.C8 75.03,57.84 74.9,57.96 74.9,60.11 75.01,60.21 75.37,60.21 75.48,60.11 75.48,59.03 75.6,58.9 75.79,58.9 75.92,59.03 75.92,60.04 76.05,60.17 76.3,60.17 76.43,60.04 76.43,59.43 76.55,59.31 76.75,59.31 76.87,59.43 76.87,60.11 76.97,60.21 77.21,60.21 77.32,60.11 77.32,59.52 77.43,59.41 77.91,59.41
  TOP w0.121: v1(78.4,59.85) 78.78,59.85 78.9,59.73 78.9,56.68 78.78,56.55 78.53,56.55 78.41,56.68 78.41,57.21 78.21,57.41 78.21,59.16 77.95,59.41 77.91,59.41
  LY3 w0.133: v1(87.22,59.16) 87.22,60.62 88.61,62.01 88.61,64.91 89.06,65.37 89.06,66.65 87.79,67.92 87.79,70.52 88.37,71.09 88.37,71.47 88.33,71.51 v1(88.33,71.57)
  BOTTOM w0.121: v1(87.22,59.16) 87.1,59.28 86.33,59.28 86.21,59.41 86.21,59.73 86.08,59.85 v1(78.4,59.85) ; v1(88.33,71.57) 87.92,71.98 R429.2
DDR_D1: length 37.6
  TOP w0.076: U8.C2 75.34,62.97 75.46,63.09 77.13,63.09 77.25,62.97 77.25,62.14
  TOP w0.121: v1(75.22,68.05) 75.22,65.82 75.35,65.7 77.12,65.7 77.76,65.06 77.76,62.14 77.63,62.01 77.38,62.01 77.25,62.14
  LY3 w0.133: v1(90.02,71.23) 90.01,71.22 89.95,71.22 89.13,70.4 89.13,69.38 v1(88.26,68.51)
  BOTTOM w0.121: v1(75.22,68.05) 75.25,68.08 75.64,68.08 75.77,68.2 75.77,68.78 76.04,69.05 76.04,69.94 76.17,70.06 78.14,70.06 78.27,69.94 78.27,69.54 78.14,69.41 76.68,69.41 76.56,69.28 76.56,68.37 76.82,68.11 77.18,68.11 77.44,68.37 77.44,68.64 77.71,68.92 86.3,68.92 86.7,68.51 v1(88.26,68.51) ; v1(90.02,71.23) 90.02,71.86 89.45,72.43 R522.2
DDR_D2: length 41.6
  TOP w0.076: 77.78,60.36 72.68,60.36 72.55,60.24 72.55,59.79 72.68,59.66 74.41,59.66 74.54,59.54 U8.D7
  TOP w0.121: 77.78,60.36 77.79,60.36 78.85,60.36 79.22,59.98 79.22,56.55 79.35,56.43 79.6,56.43 79.73,56.55 v1(79.73,60.49) ; v1(88.11,59.22) 88.11,60.06 89.12,61.07 89.12,64.7 90.72,66.31 90.72,68.37 91.67,69.32 R523.2
  BOTTOM w0.121: v1(79.73,60.49) 79.74,60.49 79.98,60.25 79.98,60.24 80.11,60.11 86.5,60.11 86.62,59.98 86.62,59.85 86.75,59.72 87.33,59.72 87.45,59.61 87.45,59.61 87.84,59.22 v1(88.11,59.22)
DDR_D3: length 39.8
  TOP w0.076: U8.D3 v1(74.94,61.44) 74.94,60.97 75.03,60.87 77.91,60.87
  TOP w0.121: v1(77,68.55) 77,66.87 77.22,66.65 77.73,66.65 77.89,66.49 77.89,65.98 78.16,65.71 78.66,65.71 78.96,65.41 78.96,63.66 79.09,63.54 79.35,63.54 79.48,63.41 79.48,63.16 79.35,63.03 79.09,63.03 78.96,62.9 78.96,62.46 79.09,62.33 79.55,62.33 79.79,62.09 79.79,61.06 79.67,60.93 79.47,60.93 79.35,61.06 79.35,61.7 79.22,61.82 78.4,61.82 78.27,61.7 78.27,61 78.14,60.87 77.91,60.87 ; R524.2 92.62,68.81 91.86,68.05 v1(91.41,68.05)
  BOTTOM w0.121: v1(77,68.55) 77.61,69.16 86.4,69.16 86.78,68.79 87.46,68.79 87.63,68.95 88.47,68.95 88.62,68.8 90.94,68.8 91.87,68.8 92.3,68.37 92.3,68.17 92.18,68.05 v1(91.41,68.05)
DDR_D4: length 40.6
  TOP w0.076: 75.03,65.06 75.03,63.93 v1(74.94,63.84) U8.D1
  TOP w0.121: v1(74.4,67.22) 74.4,66.52 74.27,66.39 73.38,66.39 73.25,66.27 73.25,65.32 73.38,65.19 74.9,65.19 75.03,65.06
  LY3 w0.133: v1(89.32,67.28) 89.7,67.66 89.7,70.01 90.52,70.84 90.52,71.47 90.52,71.47 90.52,71.8 90.02,72.3 90.02,73.24 90.27,73.5 v1(90.27,73.95)
  BOTTOM w0.121: R525.2 90.08,73.76 v1(90.27,73.95) ; v1(74.4,67.22) 74,67.22 73.54,67.68 73.27,67.68 72.43,68.52 72.43,69.63 72.93,70.13 73.42,70.13 73.75,70.46 74.33,70.46 74.46,70.33 74.46,69.89 74.33,69.76 74.05,69.76 73.93,69.63 73.93,68.65 73.76,68.49 73.76,68.12 74.02,67.86 74.43,67.86 74.8,67.5 74.94,67.35 75.76,67.35 76,67.59 77.79,67.59 78.09,67.29 79.23,67.29 80.1,68.16 80.22,68.16 80.24,68.17 85.99,68.17 86.63,67.53 88.8,67.53 89.04,67.28 v1(89.32,67.28)
DDR_D5: length 44.2
  TOP w0.076: U8.D9 74.54,56.36 ; 77.72,60.62 72.49,60.62 72.36,60.49 72.36,59.6 72.49,59.47 73.95,59.47 74.08,59.35 74.08,56.36
  TOP w0.121: v1(78.9,61.19) 78.33,60.62 77.72,60.62 ; 74.08,56.36 74.08,54.2 74.21,54.08 74.41,54.08 74.54,54.2 74.54,56.36
  LY3 w0.133: v1(87.73,60.3) 88.87,61.44 88.87,64.81 90.48,66.41 90.48,68.51 91.46,69.49 91.46,73.01 91.16,73.31 v1(91.16,73.89)
  BOTTOM w0.121: v1(91.16,73.89) 91.16,74.65 R526.2 ; v1(78.9,61.19) 79.19,61.19 79.25,61.24 80.87,61.24 81.13,61.5 81.57,61.5 82.4,60.68 87.35,60.68 v1(87.73,60.3)
DDR_D6: length 38.1
  TOP w0.076: 76.54,65.16 v1(76.54,63.84) U8.B1
  TOP w0.121: v1(91.29,66.97) 90.97,67.28 90.97,68.24 92.18,69.45 v1(92.18,71.47) ; v1(74.21,68.3) 74.21,68.3 74.84,67.67 74.84,67.03 74.84,67.02 74.84,66.27 74.71,66.14 73.63,66.14 73.5,66.01 73.5,65.57 73.63,65.44 76.25,65.44 76.54,65.16
  BOTTOM w0.121: v1(92.18,71.47) 92.24,71.53 R527.2 ; v1(74.21,68.3) 74.21,69.38 74.33,69.51 75.67,69.51 75.79,69.38 75.79,69.15 75.67,69.03 74.91,69.03 74.78,68.9 74.78,67.87 75.04,67.6 75.65,67.6 75.89,67.84 76.01,67.84 76.02,67.85 77.89,67.85 78.2,67.54 79.13,67.54 80.01,68.42 86.09,68.42 86.23,68.28 86.72,67.79 89.51,67.79 89.77,67.53 90.2,67.53 90.77,66.97 v1(91.29,66.97)
DDR_D7: length 37.6
  TOP w0.121: v1(89.64,64.36) 89.64,64.87 91.1,66.33 91.97,66.33 93.89,68.25 v1(93.89,70.84) ; U8.B9 76.14,54.46 76.26,54.33 80.68,54.33 80.81,54.46 80.81,61.19 81.25,61.63 81.25,65.38 v1(81.13,65.51)
  BOTTOM w0.076: 89.3,64.7 v1(89.64,64.36)
  BOTTOM w0.121: 89.3,64.7 88.8,64.7 88,64.7 87.99,64.71 87.13,64.71 86.9,64.94 86.87,64.94 86.86,64.94 86.26,64.94 85.76,65.44 83.49,65.44 83.35,65.59 81.21,65.59 v1(81.13,65.51) ; R528.2 93.38,71.35 v1(93.89,70.84)
